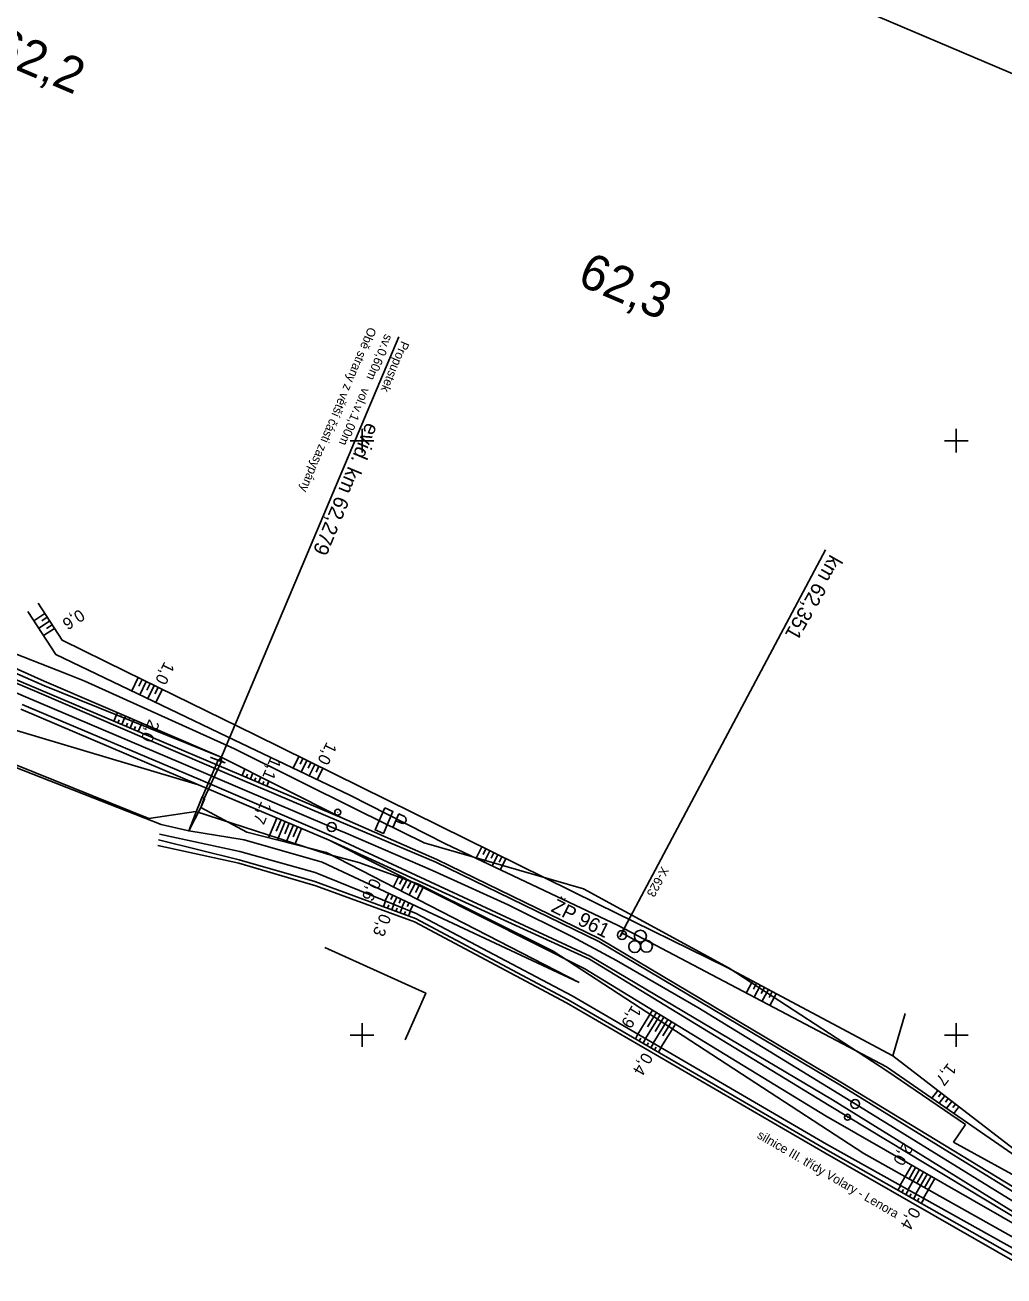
# Model space of a CAD drawing. Extents: x -805636 to -804553, y -1165340 to -1164656.
# Drawn here: x -805256.7 to -805092, y -1165040.5 to -1164830.1 of the extents above; entities that cross this region are included whole.
import ezdxf

# ---------------------------------------------------------------- set-up
doc = ezdxf.new("R2010")
doc.units = 0
for name, color, linetype in [('0381KM061-064P - Vrstva 1', 7, 'Continuous'), ('0381KM061-064P - Vrstva 17', 7, 'Continuous'), ('0381KM061-064P - Vrstva 19', 7, 'Continuous'), ('0381KM061-064P - Vrstva 23', 7, 'Continuous'), ('0381KM061-064P - Vrstva 33', 7, 'Continuous'), ('0381KM061-064P - Vrstva 4', 7, 'Continuous'), ('0381KM061-064P - Vrstva 48', 7, 'Continuous'), ('0381KM061-064P - Vrstva 49', 7, 'Continuous'), ('0381KM061-064P - Vrstva 51', 7, 'Continuous'), ('0381KM061-064P - Vrstva 7', 7, 'Continuous'), ('0381KM061-064P - Vrstva 8', 7, 'Continuous'), ('formát', 7, 'Continuous'), ('hran DP - hran DP', 7, 'Continuous'), ('krizky_1000 - Vrstva 1', 7, 'Continuous'), ('vyt_sit - stávající', 7, 'Continuous')]:
    doc.layers.add(name, color=color, linetype=linetype)

msp = doc.modelspace()

# ---------------------------------------------------------------- linework, layer by layer
at = {"layer": '0381KM061-064P - Vrstva 1'}
for points in [[(-805344.65, -1164905.78), (-805313.66, -1164918.88), (-805286.17, -1164930.55), (-805256.63, -1164943.09), (-805230.48, -1164954.2), (-805205.12, -1164965.01), (-805202.66, -1164966.06)], [(-805202.66, -1164966.06), (-805188.16, -1164972.33), (-805175.38, -1164978.12)], [(-805175.38, -1164978.12), (-805164.58, -1164983.51), (-805157.2, -1164987.48)], [(-805157.2, -1164987.48), (-805143.51, -1164995.39), (-805131.47, -1165002.7)], [(-805131.47, -1165002.7), (-805117.01, -1165011.6), (-805094.55, -1165025.46), (-805076.19, -1165036.77)]]:
    msp.add_lwpolyline(points, dxfattribs=at)
at = {"layer": '0381KM061-064P - Vrstva 17'}
msp.add_lwpolyline([(-805108.59, -1164996.37), (-805110.66, -1165003.53), (-805138.64, -1164988.6), (-805160.38, -1164977.95), (-805217.98, -1164949.5), (-805239.73, -1164938.85), (-805250.48, -1164933.58), (-805254.52, -1164927.32)], dxfattribs=at)
at = {"layer": '0381KM061-064P - Vrstva 19'}
msp.add_line((-805223.94, -1164953.85), (-805193.79, -1164882.51), dxfattribs=at)
for points in [[(-805225.46, -1164953.29), (-805223.07, -1164954.18)], [(-805223.07, -1164954.18), (-805223.66, -1164953.94), (-805223.66, -1164953.95), (-805224.21, -1164953.74), (-805224.2, -1164953.73), (-805225.46, -1164953.29), (-805225.46, -1164953.29)], [(-805224.2, -1164953.73), (-805226.95, -1164960.17)], [(-805223.66, -1164953.94), (-805226.63, -1164960.32)], [(-805226.95, -1164960.17), (-805227.7, -1164961.91), (-805226.89, -1164959.92)], [(-805226.63, -1164960.32), (-805227.14, -1164961.71), (-805226.51, -1164960.3)], [(-805226.95, -1164960.17), (-805226.89, -1164959.92), (-805226.51, -1164960.3), (-805226.63, -1164960.32)]]:
    msp.add_lwpolyline(points, dxfattribs=at)
at = {"layer": '0381KM061-064P - Vrstva 23'}
msp.add_lwpolyline([(-805206.24, -1164985.26), (-805189.29, -1164992.96), (-805192.75, -1165000.8)], dxfattribs=at)
at = {"layer": '0381KM061-064P - Vrstva 33'}
msp.add_lwpolyline([(-805196.16, -1164961.8), (-805194.79, -1164962.4), (-805196.4, -1164966.09), (-805197.77, -1164965.49)], close=True, dxfattribs=at)
for points in [[(-805194.83, -1164965.11), (-805193.83, -1164962.81)], [(-805193.37, -1164964.36), (-805194.33, -1164963.94)], [(-805193.83, -1164962.81), (-805192.88, -1164963.22)], [(-805192.88, -1164963.22), (-805192.63, -1164963.45), (-805192.59, -1164963.91), (-805192.68, -1164964.11), (-805193.04, -1164964.4), (-805193.37, -1164964.36)]]:
    msp.add_lwpolyline(points, dxfattribs=at)
at = {"layer": '0381KM061-064P - Vrstva 4'}
for points in [[(-805364.7, -1164895.97), (-805343.19, -1164904.86), (-805317.03, -1164915.68), (-805296.75, -1164924.42), (-805284.83, -1164929.56), (-805254.7, -1164942.26), (-805226.16, -1164954.55), (-805203.52, -1164964.18), (-805187.57, -1164970.92)], [(-805364.7, -1164895.97), (-805342.91, -1164904.36), (-805316.81, -1164915.12), (-805296.46, -1164924.13), (-805284.52, -1164929.13), (-805254.45, -1164941.83), (-805225.92, -1164953.93), (-805203.38, -1164963.47), (-805187.4, -1164970.45)], [(-805257.21, -1164944.39), (-805227.21, -1164957.06), (-805205.17, -1164966.48), (-805161.59, -1164986.72), (-805120.84, -1165010.88), (-805082.03, -1165034.98)], [(-805257.4, -1164945.18), (-805227.5, -1164957.9), (-805205.55, -1164967.2), (-805161.7, -1164987.26), (-805121.4, -1165011.84), (-805082.08, -1165035.58)], [(-805187.57, -1164970.92), (-805160.12, -1164984.24), (-805119.58, -1165008.37), (-805080.47, -1165032.5)], [(-805187.4, -1164970.45), (-805159.98, -1164983.82), (-805119.44, -1165007.96), (-805080.11, -1165031.8)]]:
    msp.add_lwpolyline(points, dxfattribs=at)
at = {"layer": '0381KM061-064P - Vrstva 48'}
for p, q in [((-805253.38, -1164929.09), (-805255.23, -1164930.29)), ((-805252.97, -1164929.72), (-805253.9, -1164930.32)), ((-805252.57, -1164930.35), (-805254.41, -1164931.54)), ((-805251.75, -1164931.61), (-805253.59, -1164932.8)), ((-805252.16, -1164930.99), (-805253.08, -1164931.58)), ((-805237.68, -1164939.86), (-805238.76, -1164942.09)), ((-805237, -1164940.19), (-805237.55, -1164941.3)), ((-805236.33, -1164940.52), (-805237.41, -1164942.74)), ((-805235.65, -1164940.85), (-805236.2, -1164941.96)), ((-805234.98, -1164941.18), (-805236.06, -1164943.39)), ((-805234.31, -1164941.51), (-805234.85, -1164942.61)), ((-805233.63, -1164941.84), (-805234.71, -1164944.04)), ((-805241.79, -1164947.2), (-805241.34, -1164946.12)), ((-805241.16, -1164945.74), (-805241.33, -1164946.13)), ((-805241.1, -1164947.49), (-805240.87, -1164946.95)), ((-805240.47, -1164946.04), (-805240.55, -1164946.22)), ((-805240.41, -1164947.78), (-805239.95, -1164946.69)), ((-805239.78, -1164946.33), (-805239.94, -1164946.69)), ((-805239.09, -1164946.63), (-805239.17, -1164946.8)), ((-805238.4, -1164946.93), (-805238.54, -1164947.25)), ((-805239.72, -1164948.07), (-805239.48, -1164947.52)), ((-805239.03, -1164948.37), (-805238.55, -1164947.25)), ((-805238.34, -1164948.66), (-805238.1, -1164948.09)), ((-805237.71, -1164947.22), (-805237.78, -1164947.38)), ((-805237.65, -1164948.95), (-805237.16, -1164947.8)), ((-805237.03, -1164947.52), (-805237.15, -1164947.81)), ((-805210.62, -1164953.13), (-805211.59, -1164955.1)), ((-805209.95, -1164953.46), (-805210.43, -1164954.44)), ((-805220.17, -1164956.36), (-805219.7, -1164955.24)), ((-805209.27, -1164953.79), (-805210.24, -1164955.75)), ((-805208.6, -1164954.13), (-805209.08, -1164955.1)), ((-805207.93, -1164954.46), (-805208.88, -1164956.39)), ((-805207.26, -1164954.79), (-805207.73, -1164955.75)), ((-805206.58, -1164955.12), (-805207.53, -1164957.04)), ((-805219.48, -1164956.65), (-805219.26, -1164956.11)), ((-805218.79, -1164956.94), (-805218.36, -1164955.91)), ((-805218.1, -1164957.23), (-805217.89, -1164956.74)), ((-805217.41, -1164957.53), (-805217.02, -1164956.59)), ((-805216.72, -1164957.82), (-805216.53, -1164957.37)), ((-805216.03, -1164958.11), (-805215.67, -1164957.27)), ((-805215.72, -1164966.81), (-805214.31, -1164963.49)), ((-805214.44, -1164965.71), (-805213.62, -1164963.78)), ((-805214.25, -1164967.18), (-805212.93, -1164964.07)), ((-805213, -1164966.17), (-805212.24, -1164964.37)), ((-805212.78, -1164967.55), (-805211.55, -1164964.66)), ((-805211.57, -1164966.63), (-805210.86, -1164964.95)), ((-805211.31, -1164967.93), (-805210.17, -1164965.24)), ((-805179.84, -1164968.33), (-805180.79, -1164970.25)), ((-805179.17, -1164968.67), (-805179.64, -1164969.62)), ((-805178.5, -1164969), (-805179.43, -1164970.9)), ((-805177.82, -1164969.33), (-805178.29, -1164970.27)), ((-805177.15, -1164969.66), (-805178.08, -1164971.54)), ((-805176.48, -1164970), (-805176.94, -1164970.93)), ((-805175.81, -1164970.33), (-805176.72, -1164972.18)), ((-805194.72, -1164975.07), (-805193.75, -1164973.14)), ((-805193.67, -1164974.64), (-805193.08, -1164973.48)), ((-805193.39, -1164975.75), (-805192.41, -1164973.81)), ((-805192.33, -1164975.32), (-805191.74, -1164974.15)), ((-805192.05, -1164976.44), (-805191.07, -1164974.49)), ((-805196.08, -1164977.43), (-805195.48, -1164976.15)), ((-805195.15, -1164977.21), (-805194.8, -1164976.47)), ((-805190.99, -1164976), (-805190.4, -1164974.83)), ((-805190.72, -1164977.12), (-805189.73, -1164975.16)), ((-805196.04, -1164977.44), (-805196.4, -1164978.43)), ((-805195.48, -1164978.11), (-805195.7, -1164978.69)), ((-805194.65, -1164978), (-805194.99, -1164978.95)), ((-805194.69, -1164977.99), (-805194.12, -1164976.79)), ((-805194.09, -1164978.65), (-805194.29, -1164979.21)), ((-805193.77, -1164977.8), (-805193.45, -1164977.11)), ((-805193.25, -1164978.56), (-805193.59, -1164979.47)), ((-805193.29, -1164978.55), (-805192.77, -1164977.42)), ((-805192.39, -1164978.4), (-805192.09, -1164977.74)), ((-805191.9, -1164979.11), (-805191.41, -1164978.06)), ((-805192.69, -1164979.2), (-805192.89, -1164979.73)), ((-805191.86, -1164979.13), (-805192.18, -1164979.99)), ((-805134.27, -1164990.93), (-805135.34, -1164992.94)), ((-805133.61, -1164991.28), (-805134.14, -1164992.29)), ((-805132.95, -1164991.64), (-805134.02, -1164993.64)), ((-805132.29, -1164991.99), (-805132.82, -1164992.99)), ((-805131.62, -1164992.34), (-805132.69, -1164994.34)), ((-805130.96, -1164992.7), (-805131.49, -1164993.69)), ((-805130.3, -1164993.05), (-805131.36, -1164995.04)), ((-805153.57, -1164999.86), (-805151.11, -1164995.82)), ((-805152.28, -1165000.61), (-805149.83, -1164996.6)), ((-805151.94, -1164998.63), (-805150.47, -1164996.21)), ((-805150.98, -1165001.37), (-805148.55, -1164997.38)), ((-805150.65, -1164999.39), (-805149.19, -1164996.99)), ((-805149.69, -1165002.12), (-805147.27, -1164998.16)), ((-805149.36, -1165000.16), (-805147.91, -1164997.77)), ((-805153.56, -1164999.87), (-805154, -1165000.63)), ((-805153.09, -1165000.55), (-805153.35, -1165001.01)), ((-805152.27, -1165000.62), (-805152.71, -1165001.38)), ((-805151.79, -1165001.3), (-805152.06, -1165001.76)), ((-805150.97, -1165001.38), (-805151.41, -1165002.14)), ((-805150.5, -1165002.06), (-805150.76, -1165002.51)), ((-805149.67, -1165002.13), (-805150.11, -1165002.89)), ((-805103.12, -1165009.34), (-805104.11, -1165010.63)), ((-805102.52, -1165009.79), (-805103.01, -1165010.42)), ((-805101.93, -1165010.25), (-805102.87, -1165011.48)), ((-805101.33, -1165010.71), (-805101.8, -1165011.31)), ((-805100.74, -1165011.17), (-805101.64, -1165012.33)), ((-805100.14, -1165011.62), (-805100.58, -1165012.19)), ((-805099.55, -1165012.08), (-805100.4, -1165013.19)), ((-805109.42, -1165025.28), (-805107.48, -1165021.9)), ((-805108.11, -1165026.01), (-805106.18, -1165022.64)), ((-805107.99, -1165024.3), (-805106.83, -1165022.27)), ((-805106.8, -1165026.74), (-805104.88, -1165023.39)), ((-805106.69, -1165025.03), (-805105.53, -1165023.01)), ((-805105.49, -1165027.48), (-805103.58, -1165024.13)), ((-805105.38, -1165025.77), (-805104.23, -1165023.76)), ((-805109.35, -1165025.32), (-805109.81, -1165026.13)), ((-805108.88, -1165026.01), (-805109.15, -1165026.5)), ((-805108.04, -1165026.05), (-805108.5, -1165026.86)), ((-805107.57, -1165026.74), (-805107.85, -1165027.23)), ((-805106.73, -1165026.78), (-805107.2, -1165027.6)), ((-805106.27, -1165027.48), (-805106.54, -1165027.97)), ((-805105.42, -1165027.51), (-805105.89, -1165028.34))]:
    msp.add_line(p, q, dxfattribs=at)
at = {"layer": '0381KM061-064P - Vrstva 49'}
for p, q in [((-805225.92, -1164953.93), (-805203.38, -1164963.47)), ((-805227.5, -1164957.9), (-805205.55, -1164967.2))]:
    msp.add_line(p, q, dxfattribs=at)
for points in [[(-805295.94, -1164922.85), (-805284.04, -1164927.86), (-805253.46, -1164941.25), (-805223.68, -1164953.23)], [(-805295.19, -1164922.01), (-805283.65, -1164926.95), (-805253.5, -1164940.46), (-805223.68, -1164953.23)], [(-805296.46, -1164924.13), (-805284.52, -1164929.13), (-805254.45, -1164941.83), (-805225.92, -1164953.93)], [(-805254.52, -1164927.32), (-805250.48, -1164933.58), (-805239.73, -1164938.85), (-805217.98, -1164949.5), (-805160.38, -1164977.95), (-805138.64, -1164988.6), (-805110.66, -1165003.53), (-805077.76, -1165028.83)], [(-805256.22, -1164928.77), (-805251.54, -1164935.95), (-805222.74, -1164949.79)], [(-805258.14, -1164948.79), (-805227.5, -1164957.9)], [(-805222.74, -1164949.79), (-805202.04, -1164959.65), (-805185.93, -1164967.81)], [(-805223.66, -1164953.94), (-805223.07, -1164954.18), (-805225.46, -1164953.29), (-805225.46, -1164953.29), (-805224.2, -1164953.73)], [(-805223.66, -1164953.94), (-805223.68, -1164953.23), (-805224.2, -1164953.73)], [(-805223.68, -1164953.23), (-805203.38, -1164963.47)], [(-805259.86, -1164954.37), (-805233.78, -1164964.57)], [(-805227.7, -1164961.91), (-805229.15, -1164965.65), (-805227.14, -1164961.71)], [(-805227.7, -1164961.91), (-805226.89, -1164959.92), (-805226.51, -1164960.3), (-805227.14, -1164961.71)], [(-805227.14, -1164961.71), (-805219.41, -1164965.87), (-805205.96, -1164969.29)], [(-805233.78, -1164964.57), (-805229.15, -1164965.65)], [(-805229.15, -1164965.65), (-805219.86, -1164967.18), (-805206.69, -1164970.91), (-805163.45, -1164991.14)], [(-805234.27, -1164967.17), (-805220.67, -1164970.52), (-805207.94, -1164974.16), (-805191.02, -1164980.42), (-805165.29, -1164994.07), (-805122, -1165019.23), (-805085.43, -1165039.91)], [(-805234.06, -1164966.19), (-805220.55, -1164969.15), (-805207.89, -1164972.65), (-805190.88, -1164979.53), (-805164.65, -1164993.41), (-805121.85, -1165018.34), (-805084.74, -1165039.06)], [(-805205.55, -1164967.2), (-805162.48, -1164988.88), (-805121.89, -1165013.64), (-805082.35, -1165036.29)], [(-805185.93, -1164967.81), (-805156.92, -1164981.59), (-805111.71, -1165005.38), (-805077.76, -1165028.83)], [(-805205.96, -1164969.29), (-805163.45, -1164991.14)]]:
    msp.add_lwpolyline(points, dxfattribs=at)
at = {"layer": '0381KM061-064P - Vrstva 51'}
msp.add_lwpolyline([(-805234.38, -1164968.09), (-805220.73, -1164971.11), (-805207.78, -1164974.89), (-805191.18, -1164980.95), (-805165.61, -1164994.58), (-805122.14, -1165019.85), (-805085.93, -1165040.55)], dxfattribs=at)
at = {"layer": '0381KM061-064P - Vrstva 7'}
for p, q in [((-805204.14, -1164962.5), (-805204.05, -1164962.54)), ((-805118.35, -1165013.81), (-805118.26, -1165013.86))]:
    msp.add_line(p, q, dxfattribs=at)
for centre, radius in [((-805204.09, -1164962.52), 0.5), ((-805205.12, -1164965.01), 0.75), ((-805117.01, -1165011.6), 0.75), ((-805118.3, -1165013.84), 0.5)]:
    msp.add_circle(centre, radius, dxfattribs=at)
at = {"layer": '0381KM061-064P - Vrstva 8'}
for p, q in [((-805156.26, -1164982.82), (-805122, -1164918.34)), ((-805155.9, -1164982.16), (-805156.62, -1164983.48)), ((-805156.26, -1164982.82), (-805153.62, -1164984.25))]:
    msp.add_line(p, q, dxfattribs=at)
for centre in [(-805153.15, -1164983.37), (-805154.1, -1164985.13), (-805152.13, -1164985.06)]:
    msp.add_circle(centre, 1, dxfattribs=at)
at = {"layer": 'formát'}
msp.add_line((-804939.6, -1164902.47), (-805519.31, -1164655.82), dxfattribs=at)
at = {"layer": 'hran DP - hran DP'}
for p, q in [((-805367.78, -1164893.1), (-805249.75, -1164939.24)), ((-805249.75, -1164939.24), (-805246.66, -1164940.48)), ((-805246.66, -1164940.48), (-805221.45, -1164951.84)), ((-805235.86, -1164963.58), (-805268.35, -1164950.48)), ((-805221.45, -1164951.84), (-805200.57, -1164962.2)), ((-805227.98, -1164962.4), (-805235.86, -1164963.58)), ((-805205.81, -1164969.6), (-805227.98, -1164962.4)), ((-805200.57, -1164962.2), (-805189.53, -1164967.68)), ((-805189.53, -1164967.68), (-805162.72, -1164975.42)), ((-805200.52, -1164970.95), (-805205.81, -1164969.6)), ((-805190.48, -1164974.63), (-805200.52, -1164970.95)), ((-805167.83, -1164985.89), (-805190.48, -1164974.63)), ((-805162.72, -1164975.42), (-805138.24, -1164988.78)), ((-805115.56, -1165019.91), (-805167.83, -1164985.89)), ((-805138.24, -1164988.78), (-805111.69, -1165006.01)), ((-805111.69, -1165006.01), (-805098.46, -1165015.06)), ((-805098.46, -1165015.06), (-805100.45, -1165018.04)), ((-805100.45, -1165018.04), (-805061.96, -1165039.19)), ((-805085.48, -1165036.81), (-805115.56, -1165019.91))]:
    msp.add_line(p, q, dxfattribs=at)
at = {"layer": 'krizky_1000 - Vrstva 1'}
for points in [[(-805200, -1164898), (-805200, -1164902)], [(-805100, -1164898), (-805100, -1164902)], [(-805202, -1164900), (-805198, -1164900)], [(-805102, -1164900), (-805098, -1164900)], [(-805200, -1164998), (-805200, -1165002)], [(-805100, -1164998), (-805100, -1165002)], [(-805202, -1165000), (-805198, -1165000)], [(-805102, -1165000), (-805098, -1165000)]]:
    msp.add_lwpolyline(points, dxfattribs=at)
at = {"layer": 'vyt_sit - stávající'}
msp.add_line((-805156.29, -1164983.15), (-805156.2, -1164983.2), dxfattribs=at)
msp.add_circle((-805156.24, -1164983.18), 0.756, dxfattribs=at)

# ---------------------------------------------------------------- texts
at = {"layer": '0381KM061-064P - Vrstva 19'}
for s, height, rotation, p in [('Obě strany z větší části zasypány', 1.5, 247.0922, (-805198.9, -1164880.77)), ('sv.0,60m   vol.v.1,00m', 1.5, 247.0922, (-805196.13, -1164881.94)), ('Propustek', 1.5, 247.0922, (-805193.37, -1164883.11)), ('evid. km 62,279', 2.5, 247.4086, (-805199.25, -1164896.81))]:
    msp.add_text(s, height=height, rotation=rotation, dxfattribs=at).set_placement(p)
at = {"layer": '0381KM061-064P - Vrstva 48'}
for s, rotation, p in [('0,6', 212.8254, (-805247.5, -1164928.26)), ('1,0', 243.9354, (-805233.24, -1164937.05)), ('2,0', 247.0311, (-805235.82, -1164946.75)), ('1,0', 243.7126, (-805205.92, -1164950.56)), ('1,1', 247.0544, (-805215.37, -1164953.11)), ('1,7', 247.0407, (-805216.94, -1164960.55)), ('0,6', 244.9302, (-805198.51, -1164973.47)), ('0,3', 249.7019, (-805196.93, -1164979.45)), ('1,9', 238.6155, (-805154.54, -1164994.87)), ('0,4', 239.8316, (-805152.65, -1165002.8)), ('1,7', 232.4407, (-805101.35, -1165004.58)), ('2,0', 240.1974, (-805108.86, -1165017.97)), ('0,4', 240.5094, (-805107.62, -1165028.78))]:
    msp.add_text(s, height=2, rotation=rotation, dxfattribs=at).set_placement(p)
at = {"layer": '0381KM061-064P - Vrstva 51'}
msp.add_text('silnice III. třídy Volary - Lenora', height=1.5, rotation=329.8239, dxfattribs=at).set_placement((-805133.64, -1165017.24))
at = {"layer": '0381KM061-064P - Vrstva 7'}
for s, rotation, p in [('62,2', 337.0034, (-805262.71, -1164835.71)), ('62,3', 336.9207, (-805163.97, -1164873.65))]:
    msp.add_text(s, height=6, rotation=rotation, dxfattribs=at).set_placement(p)
at = {"layer": '0381KM061-064P - Vrstva 8'}
for s, height, rotation, p in [('km 62,351', 2.5, 240.4167, (-805121.2, -1164919.01)), ('X-623', 1.5, 241.514, (-805149.6, -1164971.53))]:
    msp.add_text(s, height=height, rotation=rotation, dxfattribs=at).set_placement(p)
at = {"layer": 'vyt_sit - stávající'}
msp.add_text('ŽP 961', height=2.4, rotation=333.5611, dxfattribs=at).set_placement((-805168.35, -1164979.13))

doc.saveas('drawing.dxf')
